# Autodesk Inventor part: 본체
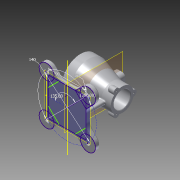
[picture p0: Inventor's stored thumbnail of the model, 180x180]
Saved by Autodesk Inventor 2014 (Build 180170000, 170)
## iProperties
Created: 2018-03
Part Number: 본체
Material: 알루미늄 6061
Document SubType Name: Modeling
Designer: kb542
Density: 2.71 g/cm^3
Appearance: 알루미늄 - 평지
Mass: 1014.98 g
Surface Area: 854.044 cm^2
Volume: 374.531 cm^3
Author: kb542
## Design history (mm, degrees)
sketch "스케치1"
  geometry: L1 (0, 0)-(100, 0); L2 (0, 35)-(23, 35); L3 (23, 35)-(23, 26); L4 (23, 26)-(70, 26); L5 (70, 26)-(70, 20); L6 (70, 20)-(100, 20); L7 (0, 35)-(0, 45); L8 (0, 45)-(20, 45); L9 (20, 45)-(77, 27.5); L10 (77, 27.5)-(100, 27.5); L11 (100, 27.5)-(100, 20); 1 further point
  constraints: 22 end point, 4 parallel, 3 perpendicular, 2 vertical alignment, 1 coincident, 1 horizontal, 1 vertical
  dimensions: "d0" = 100 distance of L1.start L1.end; "d1" = 20 distance of L7.end L8.end; "d3" = 77 distance from line of L9.end L7; "d4" = 40 diameter of L6 L1; "d5" = 55 diameter of L10 L1; "d6" = 30 distance of L5.end L6.end; "d7" = 23 distance of L2.start L2.end; "d8" = 52 diameter of L4 L1; "d9" = 70 diameter of L2 L1; "d10" = 90 diameter of L8 L1
revolve "회전1" sketch "스케치1" stored, may be unused: angle "d11" = 90 deg
sketch "스케치2"
  geometry: C1 r 7 at (0, 27.5); 1 further point
  constraints: 2 vertical alignment, 1 centre point, 1 other
  dimensions: "d13" = 7 radius of C1
extrude "돌출1" join sketch "스케치2" distance "d14" = 15; taper "d15" = 0 deg
hole "구멍1" diameter "d18" = 3.242; stored, may be unused: countersink angle "d22" = 90 deg, drill point angle "d24" = 118 deg; dims "d16" = 10, "d17" = 10, "d19" = 9, "d20" = 4, "d21" = 2, "d23" = 11
fillet "모깎기1" dims "d25" = 3, "d26" = 1
fillet "모깎기2" dims "d30" = 3
chamfer "모따기1" distance "d31" = 1; stored, may be unused: second distance "d32" = 2, angle "d33" = 45 deg
fillet "모깎기3" dims "d34" = 3
node "작업 평면1"
sketch "스케치3"
  geometry: L1 (-62.5, 12.5)-(-37.5, 12.5); L2 (-37.5, 12.5)-(-37.5, -12.5); L3 (-37.5, -12.5)-(-62.5, -12.5); L4 (-62.5, -12.5)-(-62.5, 12.5); L5 (0, 45)-(0, -45) reference; L6 (-42.5, 7.5)-(-57.5, 7.5); L7 (-57.5, 7.5)-(-57.5, -7.5); L8 (-57.5, -7.5)-(-42.5, -7.5); L9 (-42.5, -7.5)-(-42.5, 7.5); L10 (-62.5, 12.5)-(-37.5, -12.5); L11 (-37.5, 12.5)-(-62.5, -12.5); 4 further points
  constraints: 20 end point, 4 parallel, 4 perpendicular, 3 midpoint, 1 horizontal, 1 horizontal alignment, 1 point on line, 3 other
  dimensions: "d36" = 25 distance of L1.start L1.end; "d37" = 15 distance of L6.start L6.end; "d38" = 50 distance from line of point (-50, 0) L5
extrude "돌출2" join sketch "스케치3" stored distance "d39" = 15; taper "d40" = 0 deg
extrude "돌출3" cut sketch "스케치3" stored distance "d41" = 15; taper "d42" = 0 deg
fillet "모깎기4" dims "d43" = 8, "d44" = 3
fillet "모깎기5" dims "d45" = 1
chamfer "모따기2" distance "d46" = 1; stored, may be unused: second distance "d47" = 2, angle "d48" = 45 deg
sketch "스케치4" dims "d49" = 80
  geometry: C1 r 45 at (0, 0) reference; C2 r 36 at (0, 0) reference; 2 further points
  constraints: 2 vertical alignment, 1 coincident, 2 other
hole "구멍2" sketch "스케치4" at (0, 40) diameter "d50" = 3.242; stored, may be unused: countersink angle "d54" = 90 deg, drill point angle "d56" = 118 deg; dims "d51" = 9, "d52" = 4, "d53" = 2, "d55" = 11
node "작업 평면2"
node "작업 평면3"
sketch "스케치5" dims "d62" = 140
  geometry: L1 (0, 45)-(0, -45) reference; L2 (-50, -98)-(-50, 98) reference; L3 (-95, 45)-(-5, 45); L4 (-5, 45)-(-5, -45); L5 (-5, -45)-(-95, -45); L6 (-95, -45)-(-95, 45); L7 (-5, 0)-(-50, 0); L8 (-50, 0)-(-99.497, 49.497); L9 (-30.456, 45)-(-5, 19.544); L10 (-95, -19.544)-(-69.544, -45); L11 (-30.456, -45)-(-5, -19.544); L12 (-50, 0)-(-99.497, 49.497); L13 (-112.225, 36.77)-(-95, 19.544); L14 (-95, 19.544)-(-69.544, 45); L15 (-86.77, 62.225)-(-69.544, 45); L16 (-50, 25.456)-(-44.088, 19.544); C1 r 18 at (-99.497, -49.497); C2 r 18 at (-0.503, -49.497); C3 r 18 at (-0.503, 49.497); A1 r 18 centre (-99.497, 49.497) between (-86.77, 62.225) and (-112.225, 36.77); 2 further points
  constraints: 28 end point, 6 parallel, 4 centre point, 4 perpendicular, 3 midpoint, 3 point on line, 3 tangent, 2 coincident, 2 point on circle, 1 horizontal, 1 horizontal alignment, 1 vertical alignment, 12 other
  dimensions: "d61" = 90 distance of L3.start L3.end; "d63" = 135 deg angle of L8 L7; "d64" = 36 diameter of A1; "d67" = 360 deg dimension on L7.end A1.centre (derived)
extrude "돌출4" join sketch "스케치5" distance "d69" = 12; taper "d70" = 0 deg
extrude "돌출6" join sketch "스케치5" distance "d107" = 12; taper "d108" = 0 deg
fillet "모깎기6" dims "d71" = 25
sketch "스케치6"
  geometry: L1 (-70, -56.65)-(-70, -36.312) reference; L2 (-70, -42)-(-70, -56.65) reference; L3 (-70, -56.65)-(-70, -42) reference; L4 (-70, -36.312)-(-70, -56.65) reference; L5 (-70, -11.7)-(-70, -36.312) reference; L6 (-70, 11.7)-(-70, -11.7) reference; L7 (-70, 36.312)-(-70, 11.7) reference; L8 (-70, 56.65)-(-70, 36.312) reference; L9 (-70, 42)-(-70, 56.65) reference; L10 (-70, 56.65)-(-70, 42) reference; L11 (-70, 36.312)-(-70, 56.65) reference; L12 (-70, 11.7)-(-70, 36.312) reference; L13 (-70, -11.7)-(-70, 11.7) reference; L14 (-70, -36.312)-(-70, -11.7) reference; L15 (0, 0)-(-70, 0); L16 (-70, -24)-(-19.496, -19.581); L17 (-70, 24)-(-19.496, 19.581); L18 (-70, 24)-(-70, -24); C1 r 44.868 at (0, 0) reference; C2 r 35 at (0, 0) reference; A1 r 40.024 centre (0, 0) between (39.782, -4.395) and (39.782, 4.395) reference; A2 r 31.735 centre (0, 0) between (31.433, -4.368) and (31.433, 4.368) reference; A3 r 27.632 centre (0, 0) between (-19.496, 19.581) and (-19.496, -19.581); 6 further points
  constraints: 8 end point, 2 point on circle, 2 symmetric about line, 1 centre point, 1 coincident, 1 collinear, 1 midpoint, 1 point on line, 8 other
  dimensions: "d75" = 24 distance from line of L16.start L15; "d76" = 95 deg angle of L5 L16
extrude "돌출5" join sketch "스케치6" stored distance "d77" = 8; taper "d78" = 0 deg
fillet "모깎기10" dims "d109" = 25
feature "리브1" dims "d80" = 1, "d81" = 8, "d82" = 0, "d83" = 0, "d84" = 1, "d85" = 1
chamfer "모따기3" distance "d86" = 3; stored, may be unused: second distance "d87" = 2, angle "d88" = 45 deg
fillet "모깎기8" dims "d89" = 3
fillet "모깎기9" dims "d90" = 3
node "작업 평면4"
sketch "스케치8"
  geometry: L1 (-50, -94.496)-(-50, 94.496) reference; 2 further points
  constraints: 1 point on line, 1 other
  dimensions: "d92" = 35 vertical distance of point (-50, 35) point (0, 0)
feature "엠보싱1" sketch "스케치8" dims "d14" = 15, "d15" = 0, "d93" = 0.5, "d94" = 0
sketch "스케치9"
  geometry: A1 r 15 centre (0.503, -49.497) between (-10.104, -38.891) and (11.109, -60.104) reference; A2 r 15 centre (99.497, -49.497) between (88.891, -60.104) and (110.104, -38.891) reference; A3 r 15 centre (99.497, 49.497) between (110.104, 38.891) and (88.891, 60.104) reference; A4 r 15 centre (0.503, 49.497) between (11.109, 60.104) and (-10.104, 38.891) reference; 13 further points
  constraints: 4 coincident
hole "구멍3" sketch "스케치9" at (0.503, 49.497), (99.497, 49.497), (99.497, -49.497), (0.503, -49.497) diameter "d95" = 10; stored, may be unused: countersink angle "d99" = 90 deg, drill point angle "d101" = 118 deg; dims "d96" = 6, "d97" = 4, "d98" = 2, "d100" = 8
fillet "모깎기11" dims "d110" = 1
node "솔리드1"
pattern_circular "원형 패턴1" dims "d28" = 360 deg
pattern_circular "원형 패턴2" dims angle "d58" = 360 deg
mirror "대칭2"
mirror "대칭3"
mirror "대칭1"
node "투영된 루프1"
sketch "스케치7"
  geometry: L1 (13, -45)-(13, -70); L2 (20.43, -44.868)-(76.57, -27.632) reference; L3 (46, -70)-(54, -70) reference; L4 (54, -70)-(46, -70) reference; L5 (50, 68)-(50, -93) reference; L6 (0, -45)-(19.55, -45) reference; 1 further point
  constraints: 2 end point, 1 perpendicular, 1 point on line, 1 vertical
  dimensions: "d79" = 37 distance between parallel lines of L1 L5
node "투영된 루프3"
other parameters: "d35" = 45, "d60" = -82, "d91" = 21.75
